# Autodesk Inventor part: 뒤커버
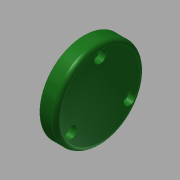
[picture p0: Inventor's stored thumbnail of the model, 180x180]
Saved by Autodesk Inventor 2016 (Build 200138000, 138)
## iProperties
Created: 2015-11
Part Number: 뒤커버
Material: 알루미늄 6061
Document SubType Name: Modeling
Designer: mduedu
Density: 1 g/cm^3
Appearance: 매끄러움 - 짙은 산림 녹색
Author: mduedu
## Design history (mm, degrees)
sketch "스케치5"
  geometry: C1 r 30 at (0, 0); 2 further points
  constraints: 2 coincident, 1 centre point
  dimensions: "d66" = 60 diameter of C1
extrude "돌출2" new body sketch "스케치5" distance "d67" = 11; taper "d68" = 0 deg
sketch "스케치6"
  geometry: C1 r 16 at (0, 0); 1 further point
  constraints: 1 centre point, 1 coincident
  dimensions: "d69" = 32 diameter of C1
extrude "돌출3" join sketch "스케치6" distance "d70" = 3; taper "d71" = 0 deg
hole "구멍5" diameter "d74" = 25; stored, may be unused: countersink angle "d78" = 90 deg, drill point angle "d80" = 0 deg; dims "d72" = 10, "d73" = 10, "d75" = 6, "d76" = 4, "d77" = 2, "d79" = 10
fillet "모깎기8" dims "d82" = 3
fillet "모깎기9" dims "d83" = 3
fillet "모깎기10" dims "d84" = 0.3
sketch "스케치7" dims "d85" = 46
  geometry: 3 further points
  constraints: 2 vertical alignment, 1 coincident, 2 other
hole "구멍6" sketch "스케치7" at (0, 23) diameter "d86" = 4.5; stored, may be unused: countersink angle "d90" = 90 deg, drill point angle "d92" = 0 deg; dims "d87" = 6, "d88" = 8, "d89" = 4.6, "d91" = 10
node "솔리드2"
pattern_circular "원형 패턴3" dims angle "d94" = 360 deg
